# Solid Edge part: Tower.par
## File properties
Title: Tower
Author: windows
Template: Iso Metric Part.par
Last saved by: windows
Revision: 5
Application: Solid Edge
Username: windows
Density: 886,000 kg/m^3
Accuracy: 0,990
Material: Polyethylene, low density
Face Style: Blue
Fill Style: ANSI34(Plastic)
Virtual Style: ANSI34(Plastic)
Grouping: Non-metals\Plastics
LibraryName: Materials
Coef. of Thermal Exp: 0.00016
Thermal Conductivity: 3.9
Specific Heat: 2219.0
Modulus of Elasticity: 144789897.0
Poisson's Ratio: 0.35
Yield Stress: 9652659.8
Ultimate Stress: 0.0
Elongation: 0.0
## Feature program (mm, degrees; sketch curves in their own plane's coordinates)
lofted protrusion "unnamed LoftedProtrusion 1"
helix protrusion "Protrusion_1"  NumberOfTurns = 4
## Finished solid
Body 1: solid body, 9 faces, 14 edges, 8 vertices, 2 separate solids.
  Faces by surface: spline 5, plane 4
  Edges by curve: line 8, spline 4, circle 2
Bounding box of the edges (mm; curved faces can reach further): 35.335 x 30.000 x 80.000, from (-15, -15, 0) to (20.3348, 15, 80).
Planar faces by outward normal: +y 1, +z 1, -y 1, -z 1
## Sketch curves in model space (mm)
line (21.9579, 0, 10) -> (21.9579, 0, 75)
circle centre (17.8348, 0, 12.5) radius 2.5
line (15, -15, 80) -> (15, 15, 80)
line (15, 15, 80) -> (-15, 15, 80)
line (-15, 15, 80) -> (-15, -15, 80)
line (-15, -15, 80) -> (15, -15, 80)
circle centre (0, 0, 50) radius 5
line (10, -10, 0) -> (10, 10, 0)
line (10, 10, 0) -> (-10, 10, 0)
line (-10, 10, 0) -> (-10, -10, 0)
line (-10, -10, 0) -> (10, -10, 0)
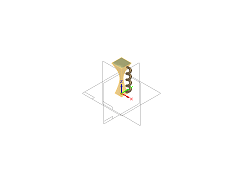
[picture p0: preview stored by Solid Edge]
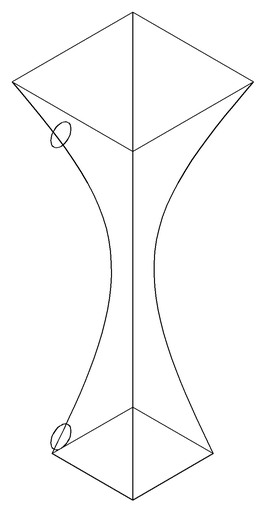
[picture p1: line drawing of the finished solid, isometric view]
